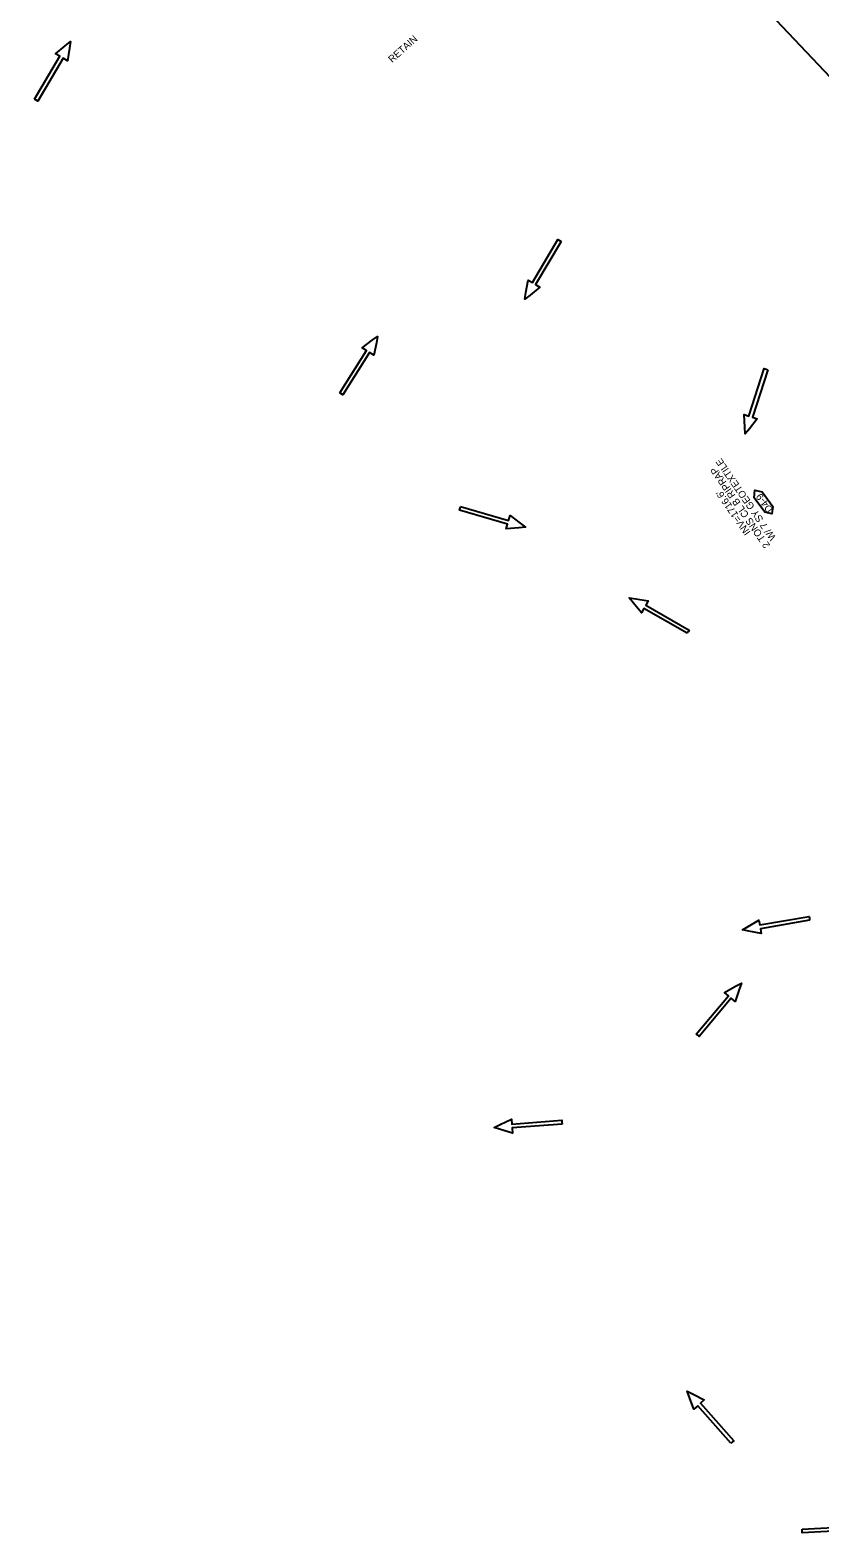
# Model space of a CAD drawing. Extents: x 465700 to 483515, y 488970 to 507540.
# Drawn here: x 474557 to 475112, y 502039 to 503099 of the extents above; entities that cross this region are included whole.
import ezdxf

# ---------------------------------------------------------------- set-up
doc = ezdxf.new("R2010")
doc.units = 0
for name, color, linetype in [('Default', 7, 'Continuous'), ('Exist Plan Preparation Drainage Flow Arrows', 7, 'Continuous'), ('Exist Plan Preparation Watershed Blue', 7, 'Continuous'), ('Prop Drainage Structure Box Number Symbol CELL', 7, 'Continuous'), ('Prop Drainage Structure Pipe Collar Label', 7, 'Continuous'), ('Prop Drainage Structure Tops and Inverts LABEL', 7, 'Continuous'), ('Prop Erosion Rip Rap Pad at Outlet Label', 7, 'Continuous')]:
    doc.layers.add(name, color=color, linetype=linetype)

# ---------------------------------------------------------------- blocks, each defined once
blk = doc.blocks.new('Existing ground flow arrow')
at = {"layer": 'Default'}
blk.add_line((2.5, -4.3), (2.5, -4.3), dxfattribs=at)
blk.add_lwpolyline([(-1.3, -47.2), (-1.3, -12.5), (-4.8, -12.5), (-1.7, -4.3), (0, 0), (1.7, -4.3), (4.8, -12.5), (1.3, -12.5), (1.3, -47.2), (0, -47.2)], close=True, dxfattribs=at)

msp = doc.modelspace()

# ---------------------------------------------------------------- linework, layer by layer
at = {"layer": 'Exist Plan Preparation Watershed Blue'}
msp.add_lwpolyline([(476013.6, 502664.4), (475829.1, 502570.5), (475740.2, 502612.1), (475654.3, 502595.4), (475588.7, 502564.1), (475566.8, 502541.8), (475566.8, 502541.8), (475478.5, 502635.6), (475391, 502718.3), (475391, 502718.3), (475391, 502718.3), (475332, 502767.3), (475336.8, 502775.2), (475334.4, 502799), (475316.9, 502836.7), (475282.1, 502903.8), (475239.6, 503008.5), (475239.6, 503008.5), (475239.6, 503008.5), (475187.6, 503080.4), (475160.2, 503050.5), (475153, 503029.9), (475043.8, 503145.6)], dxfattribs=at)
at = {"layer": 'Prop Drainage Structure Box Number Symbol CELL'}
msp.add_lwpolyline([(475073.3, 502759.8), (475065.9, 502770), (475066.2, 502775.2), (475071.4, 502774.1), (475078.8, 502763.9), (475078.2, 502758.6), (475073.3, 502759.8)], dxfattribs=at)

# ---------------------------------------------------------------- block references
at = {"layer": 'Exist Plan Preparation Drainage Flow Arrows'}
for p, xscale, yscale, rotation in [((474585.3, 503090.6), 1.0124070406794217, 1.0124070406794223, -30.454290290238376), ((474904.6, 502909.6), 1.012407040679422, 1.0124070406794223, 149.45535770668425), ((474801.1, 502883.4), 1.0124070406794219, 1.0124070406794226, -32.270243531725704), ((475059.5, 502814.9), 1.0124070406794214, 1.0124070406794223, 162.15678783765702), ((474905, 502749.2), 1.0124070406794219, 1.0124070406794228, -106.21493938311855), ((474978, 502699.6), 1.0124070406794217, 1.0124070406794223, 60.095260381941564), ((475057.5, 502466.1), 1.012407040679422, 1.0124070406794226, 99.95985540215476), ((475056.8, 502428.7), 1.012407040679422, 1.0124070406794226, -39.95895098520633), ((474883, 502327.2), 1.012407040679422, 1.0124070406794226, 94.52220372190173), ((475018.7, 502141.9), 1.012407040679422, 1.0124070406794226, 41.62517562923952), ((475147.2, 502046), 1.012407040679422, 1.0124070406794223, -87.10033738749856)]:
    msp.add_blockref('Existing ground flow arrow', p, dxfattribs=dict(at, xscale=xscale, yscale=yscale, rotation=rotation))

# ---------------------------------------------------------------- texts
at = {"layer": 'Prop Drainage Structure Box Number Symbol CELL'}
msp.add_text('D4-9', height=5, rotation=125.9045, dxfattribs=at).set_placement((475079.2, 502761.8))
at = {"layer": 'Prop Drainage Structure Pipe Collar Label'}
msp.add_text('RETAIN', height=5, rotation=41.6222, dxfattribs=at).set_placement((474811.3, 503075.5))
at = {"layer": 'Prop Drainage Structure Tops and Inverts LABEL'}
msp.add_text("INV=1716.6'", height=5, rotation=124.6912, dxfattribs=at).set_placement((475063.5, 502745.7))
at = {"layer": 'Prop Erosion Rip Rap Pad at Outlet Label'}
for s, p in [('W/ 7 SY GEOTEXTILE', (475081.4, 502742)), ('2 TONS CL B RIPRAP', (475077.2, 502736.6))]:
    msp.add_text(s, height=5, rotation=124.6912, dxfattribs=at).set_placement(p)

doc.saveas('drawing.dxf')
